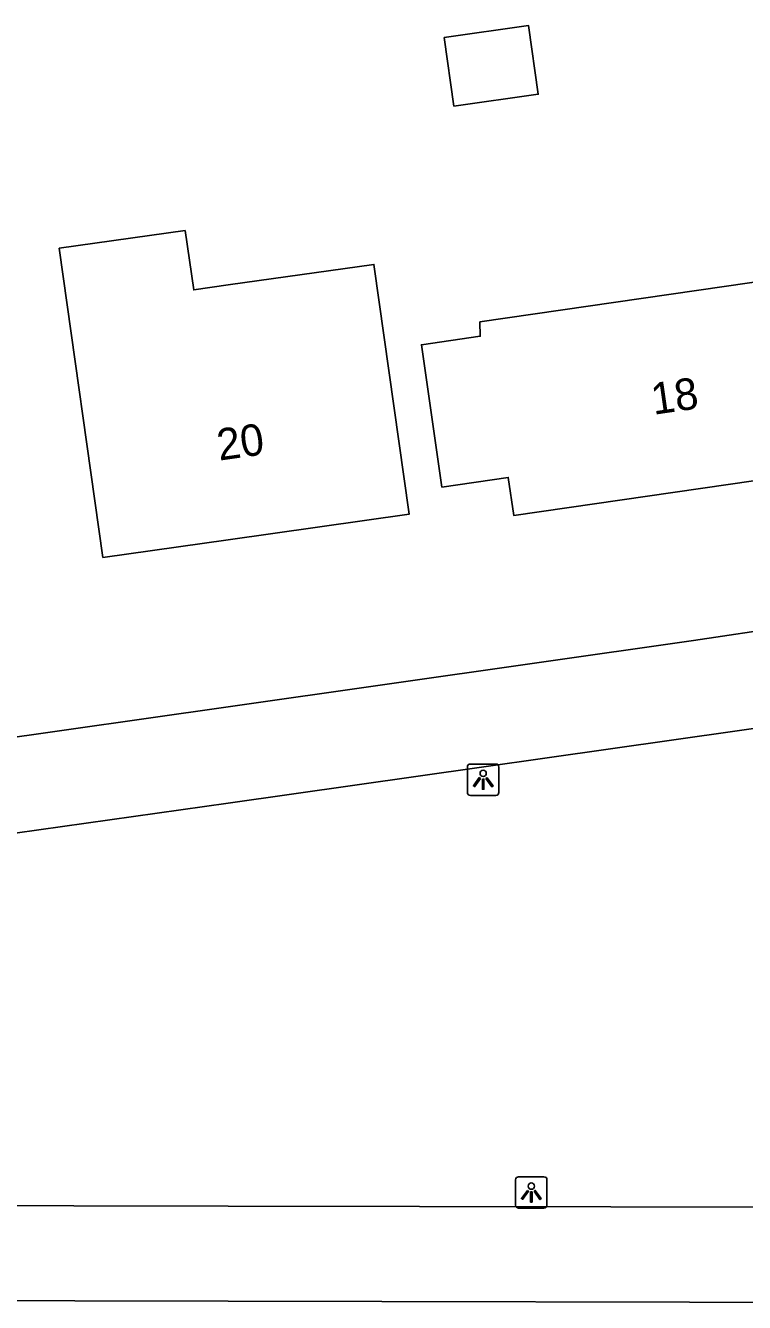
# Model space of a CAD drawing. Extents: x 162675 to 163482, y 379761 to 381227.
# Drawn here: x 162993.57 to 163016.37, y 380629.51 to 380670.01 of the extents above; entities that cross this region are included whole.
import ezdxf

# ---------------------------------------------------------------- set-up
doc = ezdxf.new("R2010")
doc.units = 0
for name, color, linetype in [('IMGEO_Lichtpunt', 7, 'Continuous'), ('IMGEO_Pand', 7, 'Continuous'), ('IMGEO_Pand_nummerreeks', 7, 'Continuous'), ('IMGEO_Rijbaan_lokaal_open', 7, 'Continuous')]:
    doc.layers.add(name, color=color, linetype=linetype)

msp = doc.modelspace()

# ---------------------------------------------------------------- linework, layer by layer
at = {"layer": 'IMGEO_Lichtpunt'}
for p, q in [((163007.585, 380646.494), (163007.585, 380645.687)), ((163007.585, 380646.494), (163007.585, 380645.687)), ((163008.487, 380646.589), (163007.679, 380646.589)), ((163008.487, 380646.589), (163007.679, 380646.589)), ((163008.581, 380645.687), (163008.581, 380646.494)), ((163008.581, 380645.687), (163008.581, 380646.494)), ((163007.679, 380645.593), (163008.487, 380645.593)), ((163007.679, 380645.593), (163008.487, 380645.593)), ((163009.11, 380633.404), (163009.11, 380632.597)), ((163009.11, 380633.404), (163009.11, 380632.597)), ((163010.012, 380633.499), (163009.204, 380633.499)), ((163010.012, 380633.499), (163009.204, 380633.499)), ((163010.106, 380632.597), (163010.106, 380633.404)), ((163010.106, 380632.597), (163010.106, 380633.404)), ((163009.204, 380632.503), (163010.012, 380632.503)), ((163009.204, 380632.503), (163010.012, 380632.503))]:
    msp.add_line(p, q, dxfattribs=at)
for points in [[(163007.959, 380646.158), (163007.998, 380646.13), (163007.81, 380645.868), (163007.772, 380645.895), (163007.959, 380646.158)], [(163008.061, 380646.11), (163008.108, 380646.11), (163008.108, 380645.788), (163008.061, 380645.788), (163008.061, 380646.11)], [(163008.171, 380646.13), (163008.209, 380646.157), (163008.396, 380645.895), (163008.357, 380645.867), (163008.171, 380646.13)], [(163009.484, 380633.068), (163009.523, 380633.04), (163009.335, 380632.778), (163009.297, 380632.805), (163009.484, 380633.068)], [(163009.586, 380633.02), (163009.633, 380633.02), (163009.633, 380632.698), (163009.586, 380632.698), (163009.586, 380633.02)], [(163009.696, 380633.04), (163009.734, 380633.067), (163009.921, 380632.805), (163009.882, 380632.777), (163009.696, 380633.04)]]:
    msp.add_lwpolyline(points, dxfattribs=at)
for centre in [(163008.084, 380646.292), (163009.609, 380633.202)]:
    msp.add_circle(centre, 0.0994, dxfattribs=at)
for centre, start, end in [((163007.679, 380646.494), 90, 180), ((163007.679, 380646.494), 90, 180), ((163008.487, 380646.494), 0, 90), ((163008.487, 380646.494), 0, 90), ((163007.679, 380645.687), 180, 270), ((163007.679, 380645.687), 180, 270), ((163008.487, 380645.687), 270, 0), ((163008.487, 380645.687), 270, 360), ((163009.204, 380633.404), 90, 180), ((163009.204, 380633.404), 90, 180), ((163010.012, 380633.404), 0, 90), ((163010.012, 380633.404), 0, 90), ((163009.204, 380632.597), 180, 270), ((163009.204, 380632.597), 180, 270), ((163010.012, 380632.597), 270, 0), ((163010.012, 380632.597), 270, 360)]:
    msp.add_arc(centre, 0.0946, start, end, dxfattribs=at)
at = {"layer": 'IMGEO_Pand'}
for points in [[(163006.851, 380669.636), (163007.158, 380667.458), (163009.832, 380667.834), (163009.525, 380670.013), (163006.851, 380669.636)], [(163007.974, 380660.614), (163019.162, 380662.23), (163018.87, 380664.245), (163021.837, 380664.675), (163022.7, 380658.716), (163019.766, 380658.291), (163020.087, 380656.074), (163009.052, 380654.477), (163008.877, 380655.68), (163006.778, 380655.376), (163006.124, 380659.89), (163007.993, 380660.16), (163007.974, 380660.614)], [(162998.636, 380663.511), (162998.906, 380661.63), (163000, 380661.784), (163004.62, 380662.434), (163005.735, 380654.513), (163000, 380653.705), (162996.026, 380653.145), (162994.645, 380662.949), (162998.636, 380663.511)]]:
    msp.add_lwpolyline(points, dxfattribs=at)
at = {"layer": 'IMGEO_Rijbaan_lokaal_open'}
for points in [[(162965.66, 380643.591), (162992.266, 380647.305), (163000, 380648.404), (163014.757, 380650.503), (163017.717, 380650.948)], [(162970.741, 380641.258), (162993.249, 380644.396), (163000, 380645.353), (163018.149, 380647.927)], [(163019.234, 380632.502), (163018.199, 380632.533), (163000, 380632.57), (162995.104, 380632.58), (162971.366, 380632.606)], [(162966.701, 380629.588), (162995.135, 380629.56), (163000, 380629.551), (163019.499, 380629.512)]]:
    msp.add_lwpolyline(points, dxfattribs=at)

# ---------------------------------------------------------------- texts
at = {"layer": 'IMGEO_Pand_nummerreeks'}
for s, rotation, p in [('18', 8.2348, (163013.484, 380657.665)), ('20', 8.0202, (162999.715, 380656.211))]:
    msp.add_text(s, height=1, rotation=rotation, dxfattribs=at).set_placement(p)

doc.saveas('drawing.dxf')
